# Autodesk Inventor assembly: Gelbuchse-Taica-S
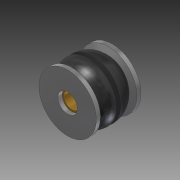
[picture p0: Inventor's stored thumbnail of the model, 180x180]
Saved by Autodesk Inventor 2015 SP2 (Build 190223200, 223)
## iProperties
Created: 2014-11
Part Number: Gelbuchse-Taica-S
Document SubType Name: Assembly
Designer: Hübner
Author: Hübner
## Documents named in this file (5)
- E:\Tigers SVN\mechanik\2016\Inventor\Kaufteile\Gelbuchse-Taica-S [entspannt].iam
- E:\Tigers SVN\mechanik\2016\Inventor\Kaufteile\Gelbuchse-Taica-S-(A) [entspannt].ipt
- E:\Tigers SVN\mechanik\2016\Inventor\Kaufteile\Gelbuchse-Taica-S-(B) [entspannt].ipt
- E:\Tigers SVN\mechanik\2016\Inventor\Kaufteile\Gelbuchse-Taica-S-(C).ipt
- E:\Tigers SVN\mechanik\2016\Inventor\Inhaltscenter\de-DE\DIN 9021\DIN 9021 - 3,7.ipt
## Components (5 placed, 4 different names)
1. Gelbuchse-Taica-S-(A) [entspannt]:1 — Passend:1, Passend:2, Einfügen:3
2. Gelbuchse-Taica-S-(B) [entspannt]:1 — Passend:1, Passend:2
3. Gelbuchse-Taica-S-(C):1 — Einfügen:3
4. DIN 9021 3,7:1
5. DIN 9021 3,7:2
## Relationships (3: Mate 2, Insert 1)
- Passend:1 [Mate]: Gelbuchse-Taica-S-(A) [entspannt]:1 ↔ Gelbuchse-Taica-S-(B) [entspannt]:1
- Passend:2 [Mate]: Gelbuchse-Taica-S-(A) [entspannt]:1 ↔ Gelbuchse-Taica-S-(B) [entspannt]:1
- Einfügen:3 [Insert]: Gelbuchse-Taica-S-(A) [entspannt]:1 ↔ Gelbuchse-Taica-S-(C):1
